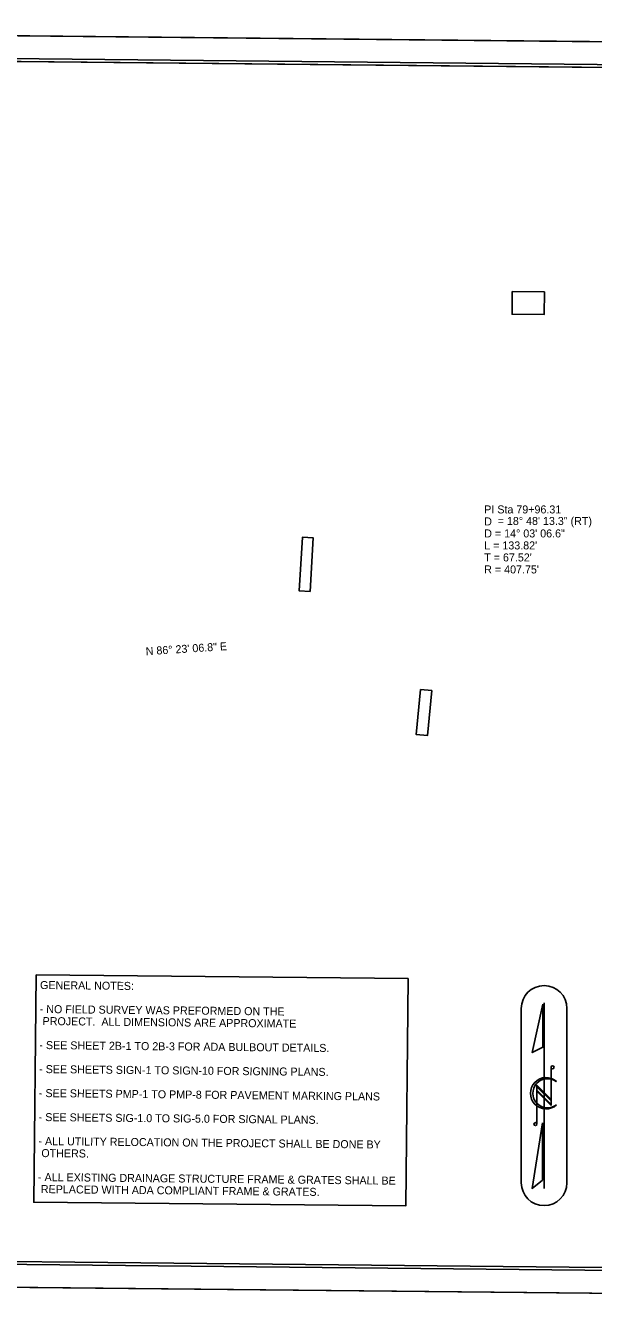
# Model space of a CAD drawing. Extents: x 928111 to 937215, y 684176 to 686530.
# Drawn here: x 933867 to 934365, y 684176 to 685288 of the extents above; entities that cross this region are included whole.
import ezdxf

# ---------------------------------------------------------------- set-up
doc = ezdxf.new("R2010")
doc.units = 0
for name, color, linetype in [('Exist Horizontal Alignment Curve and Spiral Data', 7, 'Continuous'), ('Exist Horizontal Alignment Direction Label', 7, 'Continuous'), ('Exist Horizontal Alignment Station Label', 7, 'Continuous'), ('Prop DSN Text', 7, 'Continuous'), ('Sheet Cutting Line CELL', 7, 'Continuous'), ('Sheet Plan CELL', 7, 'Continuous'), ('Sheet Plan Layout CELL', 7, 'Continuous'), ('Sheet Plot Border Inside CELL', 7, 'Continuous'), ('Sheet Plot Border Outside CELL', 7, 'Continuous')]:
    doc.layers.add(name, color=color, linetype=linetype)

msp = doc.modelspace()

# ---------------------------------------------------------------- linework, layer by layer
at = {"layer": 'Exist Horizontal Alignment Station Label'}
for p, q in [((934301.4, 684275.4), (934301.4, 684427.9)), ((934341.4, 684427.9), (934341.4, 684275.4))]:
    msp.add_line(p, q, dxfattribs=at)
for centre, start, end in [((934321.4, 684427.9), 90, 180), ((934321.4, 684427.9), 0, 90), ((934321.4, 684275.4), 180, 270), ((934321.4, 684275.4), 270, 0)]:
    msp.add_arc(centre, 20, start, end, dxfattribs=at)
at = {"layer": 'Prop DSN Text'}
for points in [[(934293.5, 685055.1), (934321.6, 685054.8), (934321.4, 685035), (934293.3, 685035.3)], [(934116.5, 684792.8), (934119.3, 684839.6), (934109.8, 684840.1), (934107, 684793.3)], [(934213.3, 684707), (934209.4, 684667.6), (934219.2, 684666.6), (934223.1, 684706)], [(933876.7, 684457.3), (934202.4, 684454), (934200.3, 684255.1), (933874.7, 684258.4)]]:
    msp.add_lwpolyline(points, close=True, dxfattribs=at)
at = {"layer": 'Sheet Cutting Line CELL'}
for p, q in [((934659.7, 685270.7), (932976.3, 685288)), ((932965.1, 684193), (934648.5, 684175.8))]:
    msp.add_line(p, q, dxfattribs=at)
at = {"layer": 'Sheet Plan CELL'}
for p, q in [((934321.4, 684270.4), (934321.4, 684432.9)), ((934327.5, 684376.4), (934327.5, 684343)), ((934327.5, 684348.2), (934315.1, 684360.7)), ((934315.1, 684360.7), (934315.1, 684326.8)), ((934327.5, 684347), (934315.1, 684359.4)), ((934315.1, 684359.4), (934315.1, 684356.4)), ((934327.5, 684344), (934315.1, 684356.4)), ((934315.1, 684356.4), (934327.5, 684344)), ((934327.5, 684343), (934315.1, 684355.5)), ((934332.1, 684364), (934332.3, 684363.8)), ((934327.5, 684344), (934327.5, 684347))]:
    msp.add_line(p, q, dxfattribs=at)
for points in [[(934642.5, 685248.4), (933142.5, 685263.8), (933131.8, 684213.8), (934631.7, 684198.5)], [(934320.3, 684431.5), (934311, 684389.3), (934320.3, 684394)], [(934320.1, 684327.7), (934310.9, 684270.4), (934320.1, 684277.7)]]:
    msp.add_lwpolyline(points, close=True, dxfattribs=at)
for centre in [(934328.8, 684376.4), (934313.8, 684326.7)]:
    msp.add_circle(centre, 1.32, dxfattribs=at)
for centre, radius, start, end in [((934323.1, 684353.7), 13.7, 47.84, 312.3941), ((934324.4, 684353.7), 12.8, 53.095, 308.6287)]:
    msp.add_arc(centre, radius, start, end, dxfattribs=at)
at = {"layer": 'Sheet Plan Layout CELL'}
msp.add_lwpolyline([(933142.5, 685263.7), (933131.8, 684213.8), (934631.7, 684198.5), (934640.3, 685037), (934401.1, 685039.4), (934403.2, 685250.9)], close=True, dxfattribs=at)
at = {"layer": 'Sheet Plot Border Inside CELL'}
msp.add_lwpolyline([(932978.3, 684212.9), (934644.2, 684195.9), (934655, 685250.8), (932989.1, 685267.8)], close=True, dxfattribs=at)
at = {"layer": 'Sheet Plot Border Outside CELL'}
msp.add_lwpolyline([(932965.1, 684193), (934648.5, 684175.8), (934659.7, 685270.7), (932976.3, 685288)], close=True, dxfattribs=at)

# ---------------------------------------------------------------- texts
at = {"layer": 'Exist Horizontal Alignment Curve and Spiral Data'}
for s, p in [('PI Sta 79+96.31', (934269, 684861)), ('D', (934269, 684850.5)), ('= 18%%d 48\' 13.3" (RT)', (934280.8, 684850.9)), ('D = 14%%d 03\' 06.6"', (934269, 684840)), ("L = 133.82'", (934269, 684829.5)), ("T = 67.52'", (934269, 684819)), ("R = 407.75'", (934269, 684808.5))]:
    msp.add_text(s, height=7, dxfattribs=at).set_placement(p)
at = {"layer": 'Exist Horizontal Alignment Direction Label'}
msp.add_text('N 86%%d 23\' 06.8" E', height=7, rotation=3.6148, dxfattribs=at).set_placement((933972.9, 684736.9))
at = {"layer": 'Prop DSN Text'}
for s, p in [('GENERAL NOTES:', (933880.2, 684444.9)), ('- NO FIELD SURVEY WAS PREFORMED ON THE ', (933879.9, 684423.9)), (' PROJECT.  ALL DIMENSIONS ARE APPROXIMATE', (933879.8, 684413.4)), ('- SEE SHEET 2B-1 TO 2B-3 FOR ADA BULBOUT DETAILS.', (933879.6, 684392.4)), ('- SEE SHEETS SIGN-1 TO SIGN-10 FOR SIGNING PLANS.', (933879.4, 684371.4)), ('- SEE SHEETS PMP-1 TO PMP-8 FOR PAVEMENT MARKING PLANS  ', (933879.2, 684350.4)), ('- SEE SHEETS SIG-1.0 TO SIG-5.0 FOR SIGNAL PLANS.', (933879, 684329.4)), ('- ALL UTILITY RELOCATION ON THE PROJECT SHALL BE DONE BY ', (933878.8, 684308.4)), (' OTHERS.', (933878.7, 684297.9)), ('- ALL EXISTING DRAINAGE STRUCTURE FRAME & GRATES SHALL BE ', (933878.4, 684276.9)), (' REPLACED WITH ADA COMPLIANT FRAME & GRATES.', (933878.3, 684266.4))]:
    msp.add_text(s, height=7, rotation=359.4141, dxfattribs=at).set_placement(p)

doc.saveas('drawing.dxf')
